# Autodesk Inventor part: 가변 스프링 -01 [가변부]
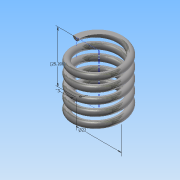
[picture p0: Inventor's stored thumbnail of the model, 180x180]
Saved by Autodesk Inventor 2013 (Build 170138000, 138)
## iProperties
Created: 2014-12
Part Number: 가변 스프링 -01 [가변부]
Material: 강철, 탄소
Document SubType Name: Modeling
Designer: Administrator
Density: 7.87 g/cm^3
Mass: 18.7386 g
Surface Area: 32.3981 cm^2
Volume: 2.38101 cm^3
Author: Administrator
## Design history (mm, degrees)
sketch "Sketch1"
  geometry: L1 (0, 0)-(11, 0); L2 (11, 0)-(11, 25.208); L3 (11, 25.208)-(0, 25.208); L4 (0, 25.208)-(0, 0); C1 r 1.5 at (11, 0)
  constraints: 8 end point, 2 parallel, 1 centre point, 1 coincident, 1 horizontal, 1 perpendicular
  dimensions: "d0" = 3 diameter of C1; "d1" = 22 diameter of L2 L4; "d2" = 25.20829 distance between parallel lines of L1 L3 (derived)
coil "Coil1" pitch "d3" = 10; turns "d5" = 5; dims "d4" = 25.20829 (= d2), "d6" = 0, angle "d7" = 90 deg, angle "d8" = 90 deg, "d9" = 0, "d10" = 0
sketch "Sketch2"
  geometry: L1 (-12.5, 0)-(-9.5, 0) reference; 1 further point
  constraints: 1 horizontal alignment
extrude "Extrusion1" cut sketch "Sketch2" stored distance "d11" = 10; taper "d12" = 0 deg
workplane "Work Plane2"
sketch "Sketch3"
  geometry: L1 (1.5, 0)-(-1.5, 0) reference; 1 further point
  constraints: 1 horizontal alignment
extrude "Extrusion2" cut sketch "Sketch3" stored distance "d14" = 10; taper "d15" = 0 deg
body "Solid1"
node "Project Cut Edges1"
node "Project Cut Edges2"
other parameters: "d13" = 0
